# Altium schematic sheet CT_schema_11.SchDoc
size 274 x 160 mm
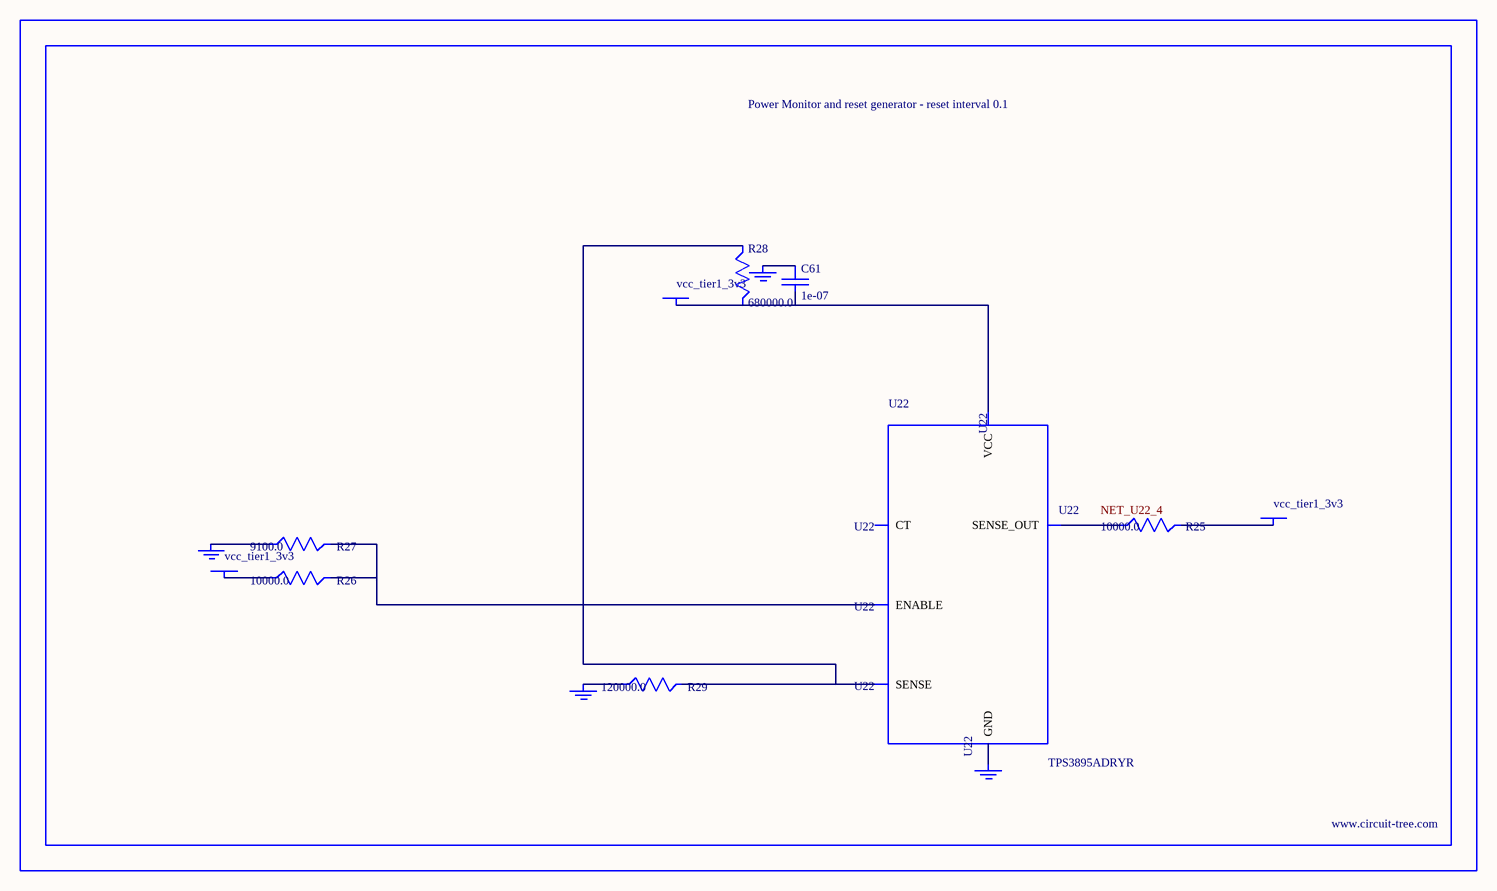
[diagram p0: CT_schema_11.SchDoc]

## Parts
BORDER10  (no value)
C61  1e-07  [C0402]
GND_INSTANCE_10_0  (no value)
GND_INSTANCE_10_1  (no value)
GND_INSTANCE_10_2  (no value)
GND_INSTANCE_10_3  (no value)
POWER_INSTANCE_10_0  vcc_tier1_3v3
POWER_INSTANCE_10_1  vcc_tier1_3v3
POWER_INSTANCE_10_2  vcc_tier1_3v3
R25  10000.0  [R0603]
R26  10000.0  [R0603]
R27  9100.0  [R0603]
R28  680000.0  [R0603]
R29  120000.0  [R0603]
U22  TPS3895ADRYR  [SON-6]

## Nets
NetC61_1: C61.1 GND_INSTANCE_10_2.0(GND)
NetC61_2: C61.2 POWER_INSTANCE_10_2.0(PWR) R28.2 U22.6(VCC)
NetGND_INSTANCE_10_0_0: GND_INSTANCE_10_0.0(GND) R27.1
NetGND_INSTANCE_10_1_0: GND_INSTANCE_10_1.0(GND) R29.1
NetGND_INSTANCE_10_3_0: GND_INSTANCE_10_3.0(GND) U22.2(GND)
NetPOWER_INSTANCE_10_0_0: POWER_INSTANCE_10_0.0(PWR) R26.1
NetPOWER_INSTANCE_10_1_0: POWER_INSTANCE_10_1.0(PWR) R25.2
NetR25_1: R25.1 U22.4(SENSE_OUT)
NetR26_2: R26.2 R27.2 U22.1(ENABLE)
NetR28_1: R28.1 R29.2 U22.3(SENSE)

Not connected (* = marked no-connect by the designer): U22 5(CT)

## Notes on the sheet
- Labels drawn without touching a wire or pin: NET_U22_4

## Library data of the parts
BORDER10 = BORDER_PAGE10
C61 = C0402C104K3RACTU
GND_INSTANCE_10_0-GND_INSTANCE_10_3 = GND
POWER_INSTANCE_10_0-POWER_INSTANCE_10_2 = PWR
R25 R26 = RC0603JR-0710KL
R27 = RC0603JR-079K1L
R28 = RC0603JR-07680KL
R29 = RC0603JR-07120KL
